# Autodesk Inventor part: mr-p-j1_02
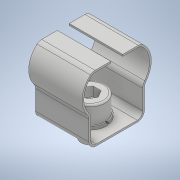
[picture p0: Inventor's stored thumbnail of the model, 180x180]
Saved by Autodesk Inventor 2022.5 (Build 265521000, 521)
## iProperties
Part Number: mr-p-j1_02
Material: 一般
Document SubType Name: Modeling
Designer: ImaoCorp
Density: 1 g/cm^3
Appearance: 既定
Author: ImaoCorp
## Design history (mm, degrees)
feature "mr-p-j1_02"
node "ソリッド1"
